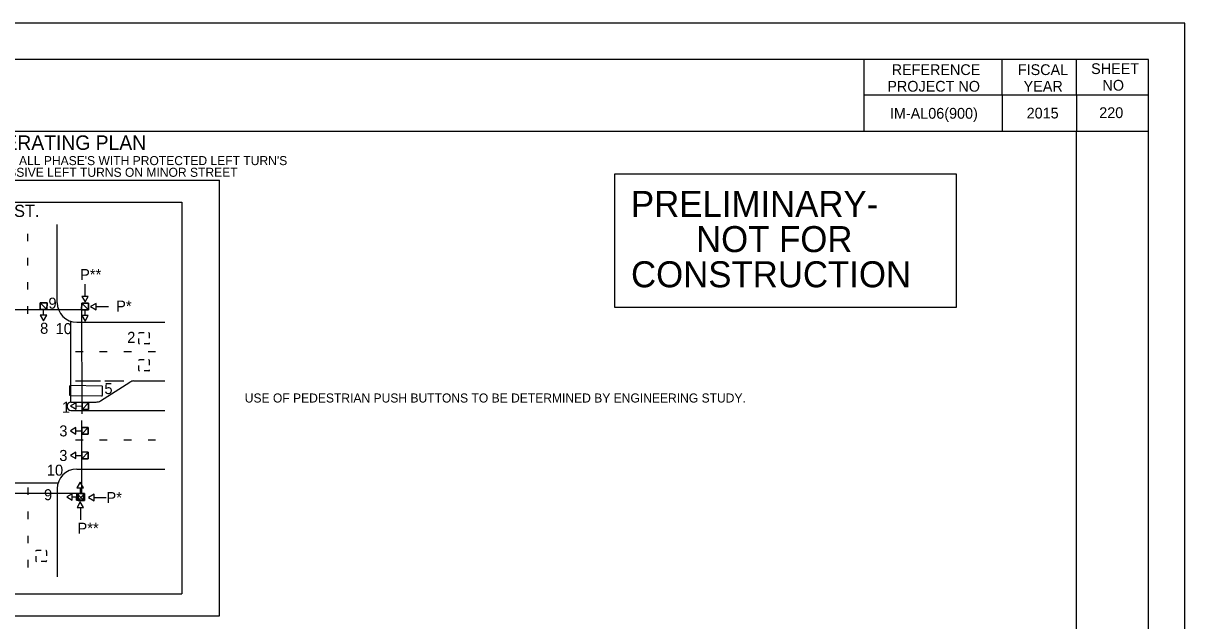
# Model space of a CAD drawing. Extents: x 515543 to 517243, y 660510 to 662861.
# Drawn here: x 516438 to 517243, y 661197 to 661610 of the extents above; entities that cross this region are included whole.
import ezdxf

# ---------------------------------------------------------------- set-up
doc = ezdxf.new("R2010")
doc.units = 0
for name, color, linetype in [('1', 7, 'Continuous'), ('2', 7, 'Continuous'), ('ANNO-SHT', 7, 'Continuous'), ('Default', 7, 'Continuous'), ('Level 6', 7, 'Continuous'), ('Level 62', 7, 'Continuous'), ('SHT-BDR', 7, 'Continuous'), ('SHT-BNDRY', 7, 'Continuous'), ('Signal Design', 7, 'Continuous')]:
    doc.layers.add(name, color=color, linetype=linetype)

# ---------------------------------------------------------------- blocks, each defined once
blk = doc.blocks.new('A$C10762150_1')
at = {"layer": 'Signal Design'}
for p, q in [((-0.33, -0.36), (0.33, 0.36)), ((-0.33, -0.36), (0.33, 0.36)), ((-0.94, -0.02), (-0.35, -0.01))]:
    blk.add_line(p, q, dxfattribs=at)
for points in [[(-0.93, -0.36), (-0.95, 0.31), (-1.52, -0.04)], [(0.35, -0.35), (-0.33, -0.36), (-0.35, 0.35), (0.33, 0.36)]]:
    blk.add_lwpolyline(points, close=True, dxfattribs=at)
for points in [[(-1.52, -0.04), (-0.93, -0.36), (-0.95, 0.31), (-1.52, -0.04)], [(-0.33, -0.36), (0.35, -0.35), (0.33, 0.36), (-0.35, 0.35), (-0.33, -0.36)]]:
    blk.add_lwpolyline(points, dxfattribs=at)
blk = doc.blocks.new('A$C57205C4C_1')
at = {"layer": 'Signal Design'}
blk.add_blockref('A$C10762150_1', (0, 0), dxfattribs=at)

msp = doc.modelspace()

# ---------------------------------------------------------------- linework, layer by layer
at = {"layer": '1'}
msp.add_lwpolyline([(516847.95, 661506.14), (517084.37, 661506.14), (517084.37, 661413.51), (516847.95, 661413.51)], close=True, dxfattribs=at)
at = {"layer": '2'}
msp.add_lwpolyline([(517167.33, 661326), (517167.38, 661321)], dxfattribs=at)
msp.add_lwpolyline([(517167.33, 661326), (517167.38, 661321)], dxfattribs=at)
at = {"layer": 'Default'}
for p, q in [((516251.21, 661501.62), (516574.21, 661501.62)), ((516574.21, 661200.31), (516574.21, 661501.62)), ((516277.29, 661486.39), (516548.12, 661486.39)), ((516548.12, 661486.39), (516548.12, 661215.55)), ((516441.61, 661459.43), (516441.61, 661464.66)), ((516441.61, 661442.7), (516441.61, 661447.93)), ((516441.61, 661425.97), (516441.61, 661431.2)), ((516481.19, 661421.26), (516481.19, 661429.72)), ((516441.61, 661409.24), (516441.61, 661414.47)), ((516488.87, 661414.2), (516497.33, 661414.2)), ((516478.88, 661412.02), (516346.82, 661412.02)), ((516479.11, 661340.08), (516478.88, 661412.02)), ((516518.26, 661392.23), (516518.27, 661389.06)), ((516522.06, 661396.05), (516518.88, 661396.04)), ((516525.88, 661392.26), (516525.87, 661395.43)), ((516474.58, 661383.04), (516479.81, 661383.04)), ((516491.31, 661383.04), (516496.54, 661383.04)), ((516508.05, 661383.04), (516513.27, 661383.04)), ((516525.25, 661388.45), (516522.08, 661388.44)), ((516524.78, 661383.04), (516530.01, 661383.04)), ((516522.06, 661377.37), (516518.88, 661377.36)), ((516525.88, 661373.57), (516525.87, 661376.75)), ((516518.26, 661373.55), (516518.27, 661370.37)), ((516525.25, 661369.76), (516522.08, 661369.75)), ((516474.58, 661362.73), (516491.8, 661362.73)), ((516494.85, 661362.73), (516508.09, 661362.73)), ((516478.91, 661313.6), (516479.07, 661335.38)), ((516474.58, 661322.1), (516479.81, 661322.1)), ((516491.31, 661322.1), (516496.54, 661322.1)), ((516508.05, 661322.1), (516513.27, 661322.1)), ((516524.78, 661322.1), (516530.01, 661322.1)), ((516478.97, 661285.04), (516478.87, 661308.9)), ((516441.61, 661289.14), (516441.61, 661283.91)), ((516346.76, 661285.04), (516478.97, 661285.04)), ((516487.45, 661282.15), (516495.92, 661282.15)), ((516441.61, 661272.41), (516441.61, 661267.18)), ((516477.95, 661275.19), (516477.95, 661266.72)), ((516441.61, 661255.67), (516441.61, 661250.44)), ((516450.8, 661245.46), (516447.63, 661245.45)), ((516441.61, 661238.94), (516441.61, 661233.71)), ((516447.01, 661241.64), (516447.02, 661238.46)), ((516454, 661237.85), (516450.83, 661237.84)), ((516454.63, 661241.66), (516454.62, 661244.84)), ((516277.29, 661215.55), (516548.12, 661215.55)), ((516251.21, 661200.31), (516574.21, 661200.31))]:
    msp.add_line(p, q, dxfattribs=at)
for points in [[(516461.93, 661416.9), (516461.93, 661471.06)], [(516481.22, 661417.41), (516483.4, 661421.28), (516478.97, 661421.24), (516481.22, 661417.41)], [(516485.02, 661414.17), (516488.89, 661411.98), (516488.85, 661416.42), (516485.02, 661414.17)], [(516471.41, 661348.17), (516471.41, 661403.98)], [(516475.47, 661403.35), (516536.41, 661403.35)], [(516470.41, 661358.97), (516470.33, 661353.26)], [(516492.7, 661359.22), (516470.99, 661359.53)], [(516491.8, 661349.01), (516512.11, 661361.89)], [(516493.18, 661352.93), (516493.26, 661358.64)], [(516515.01, 661362.73), (516536.41, 661362.73)], [(516470.89, 661352.68), (516492.6, 661352.36)], [(516468.7, 661345.13), (516468.7, 661345.46)], [(516471.41, 661348.17), (516488.9, 661348.17)], [(516471.41, 661342.42), (516536.41, 661342.42)], [(516475.47, 661301.79), (516536.41, 661301.79)], [(516406.74, 661292.31), (516462.55, 661292.31)], [(516461.93, 661288.25), (516461.93, 661227.31)], [(516477.92, 661279.04), (516475.73, 661275.17), (516480.17, 661275.21), (516477.92, 661279.04)], [(516483.6, 661282.11), (516487.47, 661279.93), (516487.43, 661284.36), (516483.6, 661282.11)]]:
    msp.add_lwpolyline(points, dxfattribs=at)
for centre, radius, start, end in [((516475.47, 661416.9), 13.54, 180, 270), ((516518.88, 661395.41), 0.635, 90.18841, 180.18841), ((516525.23, 661395.43), 0.635, 0.18841, 90.18841), ((516518.91, 661389.06), 0.635, 180.18841, 270.18841), ((516525.25, 661389.08), 0.635, 270.18841, 0.18841), ((516518.88, 661376.72), 0.635, 90.18841, 180.18841), ((516525.23, 661376.74), 0.635, 0.18841, 90.18841), ((516518.91, 661370.38), 0.635, 180.18841, 270.18841), ((516525.25, 661370.4), 0.635, 270.18841, 0.18841), ((516470.99, 661358.96), 0.571, 89.16504, 179.16504), ((516492.69, 661358.65), 0.571, 359.16504, 89.16504), ((516515.01, 661357.31), 5.42, 90, 122.37247), ((516470.9, 661353.25), 0.571, 179.16504, 269.16504), ((516492.61, 661352.93), 0.571, 269.16504, 359.16504), ((516471.41, 661345.46), 2.71, 90, 180), ((516471.41, 661345.13), 2.71, 180, 270), ((516488.9, 661353.59), 5.42, 270, 302.37247), ((516475.47, 661288.25), 13.54, 90, 180), ((516447.63, 661244.81), 0.635, 90.18841, 180.18841), ((516453.98, 661244.83), 0.635, 0.18841, 90.18841), ((516447.65, 661238.47), 0.635, 180.18841, 270.18841), ((516454, 661238.49), 0.635, 270.18841, 0.18841)]:
    msp.add_arc(centre, radius, start, end, dxfattribs=at)
at = {"layer": 'Level 6'}
for p, q in [((517020.23, 661585.25), (517020.23, 661535.3)), ((517116.05, 661560.26), (517116.05, 661585.26)), ((517167.5, 661560.91), (517167.5, 661585.26)), ((517217.52, 661560.55), (517020.23, 661560.55)), ((517116.05, 661560.26), (517116.05, 661535.3)), ((517167.5, 661560.91), (517167.5, 661535.3)), ((517217.52, 661535.3), (517026.28, 661535.3))]:
    msp.add_line(p, q, dxfattribs=at)
at = {"layer": 'Level 62'}
msp.add_lwpolyline([(515542.51, 660510.25), (517242.52, 660510.25), (517242.52, 661610.25), (515542.51, 661610.25)], close=True, dxfattribs=at)
at = {"layer": 'SHT-BDR'}
msp.add_lwpolyline([(515667.5, 660585.3), (517167.5, 660585.3), (517167.5, 661535.3), (515667.5, 661535.3)], close=True, dxfattribs=at)
at = {"layer": 'SHT-BNDRY'}
msp.add_lwpolyline([(515605.01, 660535.25), (517217.52, 660535.25), (517217.52, 661585.25), (515605.01, 661585.25)], close=True, dxfattribs=at)
at = {"layer": 'Signal Design'}
for points in [[(516481.22, 661417.41), (516481.22, 661417.41), (516483.4, 661421.28), (516478.97, 661421.24)], [(516485.02, 661414.17), (516485.02, 661414.17), (516488.89, 661411.98), (516488.85, 661416.42)], [(516477.92, 661279.04), (516477.92, 661279.04), (516475.73, 661275.17), (516480.17, 661275.21)], [(516483.6, 661282.11), (516483.6, 661282.11), (516487.47, 661279.93), (516487.43, 661284.36)]]:
    msp.add_lwpolyline(points, close=True, dxfattribs=at)

# ---------------------------------------------------------------- block references
for p, xscale, yscale, rotation in [((516452.49, 661414.46), 6.664206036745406, 6.664206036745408, 88.26073256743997), ((516481.25, 661414.26), 6.664206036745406, 6.664206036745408, 88.26073256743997), ((516481.36, 661345.4), 6.664206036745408, 6.664206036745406, -1.739267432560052), ((516481.16, 661328.23), 6.664206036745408, 6.664206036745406, -1.739267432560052), ((516481.16, 661311.23), 6.664206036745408, 6.664206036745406, -1.739267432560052), ((516478.63, 661282.47), 6.664206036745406, 6.664206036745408, -1.7392674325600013), ((516477.77, 661282.55), 6.664206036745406, 6.664206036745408, -91.73926743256)]:
    msp.add_blockref('A$C57205C4C_1', p, dxfattribs=dict(at, xscale=xscale, yscale=yscale, rotation=rotation))

# ---------------------------------------------------------------- texts
at = {"layer": '1'}
for s, p in [('PRELIMINARY-', (516859.13, 661476.26)), ('NOT FOR', (516904.16, 661451.91)), ('CONSTRUCTION', (516859.16, 661427.56))]:
    msp.add_text(s, height=18, dxfattribs=at).set_placement(p)
at = {"layer": 'ANNO-SHT'}
for s, height, p in [('IM-AL06(900)', 7.4493, (517038.37, 661544.2)), ('2015', 7.449, (517133.04, 661544.36)), ('220', 7.449, (517183.3, 661544.65))]:
    msp.add_text(s, height=height, dxfattribs=at).set_placement(p)
at = {"layer": 'Default'}
for s, height, p in [('TRAFFIC SIGNAL OPERATING PLAN', 10, (516293.14, 661522.64)), ("5-8 PHASE FULLY ACTUATED WITH PEDESTRIAN FEATURES ALL PHASE'S WITH PROTECTED LEFT TURN'S", 6.25, (516188.42, 661512.09)), ('ON MAJOR STREET AND PROTECTED AND PERMISSIVE LEFT TURNS ON MINOR STREET', 6.25, (516226.01, 661504)), ('MINOR ST.', 8.464, (516391.18, 661476.2)), ('USE OF PEDESTRIAN PUSH BUTTONS TO BE DETERMINED BY ENGINEERING STUDY.', 6.25, (516591.76, 661347.84)), ('10', 7.617, (516454.69, 661297.22)), ('9', 7.62, (516452.76, 661280.24)), ('P*', 7.617, (516495.97, 661278.27)), ('P**', 7.617, (516475.94, 661257.06))]:
    msp.add_text(s, height=height, dxfattribs=at).set_placement(p)
for s, height, p in [('P**', 7.617, (516477.71, 661432.59)), ('9', 7.62, (516455.82, 661412.76)), ('P*', 7.617, (516502.68, 661410.74)), ('8', 7.62, (516450.06, 661395.39)), ('10', 7.617, (516460.79, 661395.16)), ('2', 7.62, (516510.38, 661389.13)), ('5', 7.62, (516494.58, 661353.67)), ('1', 7.62, (516465.25, 661340.77)), ('3', 7.62, (516463.35, 661324.39)), ('3', 7.62, (516463.35, 661307.39))]:
    msp.add_text(s, height=height, rotation=360, dxfattribs=at).set_placement(p)
at = {"layer": 'Level 6'}
for s, p in [('SHEET', (517177.69, 661575.11)), ('REFERENCE', (517039.6, 661574.41)), ('FISCAL', (517126.95, 661574.41)), ('PROJECT NO', (517036.6, 661562.91)), ('YEAR', (517130.95, 661562.91)), ('NO', (517185.53, 661563.61))]:
    msp.add_text(s, height=7.442, dxfattribs=at).set_placement(p)

doc.saveas('drawing.dxf')
